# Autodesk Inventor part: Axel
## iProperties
Shininess: 64.0
Angle Display Precision: 2
Document Length Units: 11269
Document Angle Units: 11279
Document Time Units: 11290
Document Mass Units: 11283
Document Length Units Precision: 3
Document Angle Units Precision: 2
Created: 2001-12
Part Number: Axel
Material: SS2172
Document SubType Name: Modeling
Designer: Tobben
Density: 1 g/cm^3
Density: 0.0
Volumn: 0.0
Area: 0.0
PropertySet Name: Model Information
Control State: 0
Master: False
Checked Out: False
Author: Tobben
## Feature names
1. Extrusion1
